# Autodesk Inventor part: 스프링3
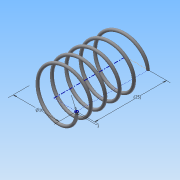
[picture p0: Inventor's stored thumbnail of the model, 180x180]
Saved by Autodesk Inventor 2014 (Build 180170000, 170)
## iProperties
Created: 2015-06
Part Number: 스프링3
Material: 강철, 연강
Document SubType Name: Modeling
Designer: Administrator
Density: 7.86 g/cm^3
Appearance: 강철
Mass: 1.52988 g
Surface Area: 7.87024 cm^2
Volume: 0.194641 cm^3
Author: Administrator
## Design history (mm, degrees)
sketch "스케치1"
  geometry: L1 (0, 0)-(8, 0); L2 (8, 0)-(8, 14.5); L3 (8, 14.5)-(0, 14.5); L4 (0, 14.5)-(0, 0); C1 r 0.5 at (8, 0)
  constraints: 8 end point, 2 parallel, 1 centre point, 1 coincident, 1 horizontal, 1 perpendicular
  dimensions: "d0" = 14.5 distance of L1.end L2.end (derived); "d1" = 16 diameter of L2 L4; "d2" = 1 diameter of C1
feature "코일1" sketch "스케치1" pitch "d3" = 10; turns "d5" = 5; dims "d4" = 14.5 (= d0), "d6" = 0, angle "d7" = 90 deg, angle "d8" = 90 deg, "d9" = 0, "d10" = 0
sketch "스케치2"
  geometry: L1 (-8.5, 0)-(-7.5, 0) reference; 1 further point
  constraints: 1 horizontal alignment
extrude "돌출1" cut sketch "스케치2" stored distance "d11" = 10; taper "d12" = 0 deg
node "작업 평면1"
sketch "스케치3"
  geometry: L1 (-7.5, 0)-(-8.5, 0) reference; 1 further point
  constraints: 1 horizontal alignment
extrude "돌출2" cut sketch "스케치3" stored distance "d14" = 10; taper "d15" = 0 deg
node "솔리드1"
node "절단 모서리 투영1"
node "절단 모서리 투영2"
other parameters: "d13" = 14.5 (= d0)
